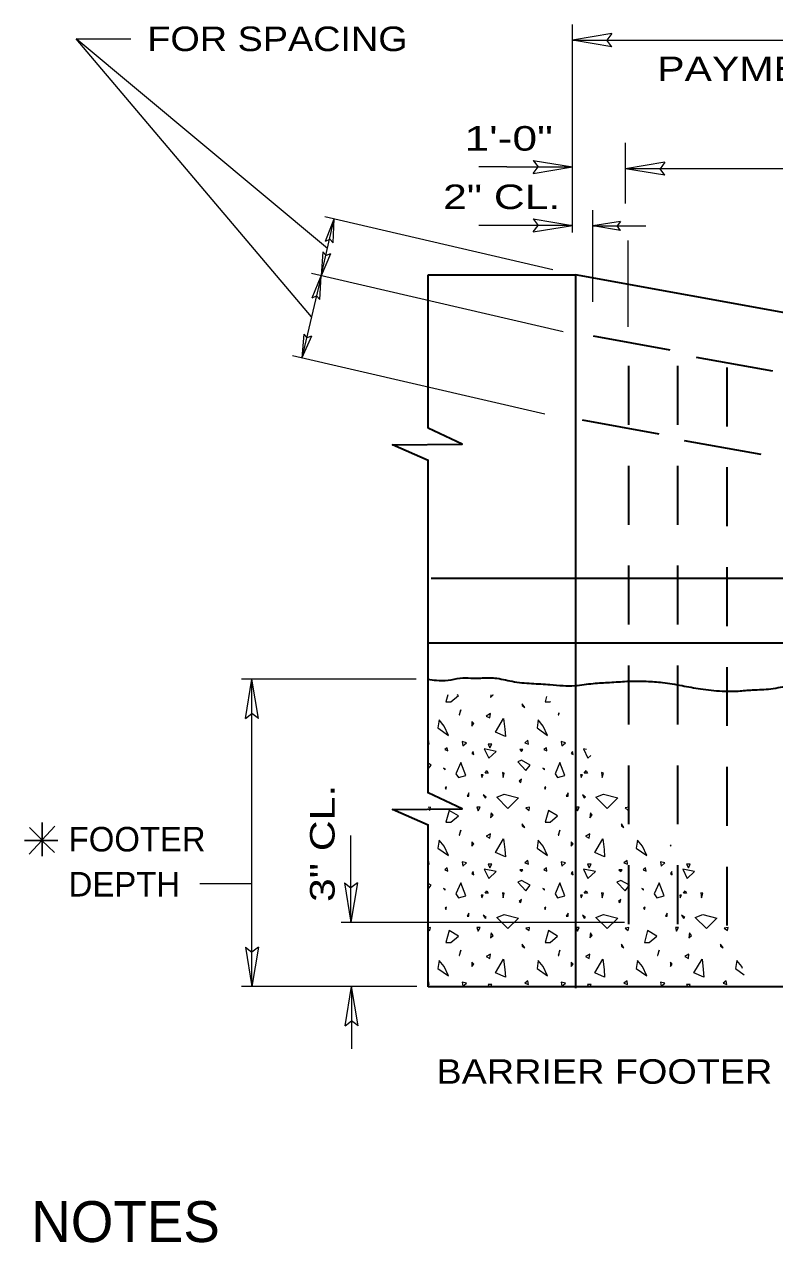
# Model space of a CAD drawing. Extents: x -15.1 to -7.9, y 13.6 to 23.8.
# Drawn here: x -15.107 to -13.275, y 16.661 to 19.638 of the extents above; entities that cross this region are included whole.
import ezdxf
from ezdxf.enums import TextEntityAlignment as Align

# ---------------------------------------------------------------- set-up
doc = ezdxf.new("R2010")
doc.units = 0
doc.header["$LTSCALE"] = 0.024
doc.linetypes.add('LONG_DASHED', pattern=[7.5, 6, -1.5])
for name, color, linetype, lineweight in [('1', 7, 'Continuous', 35), ('10', 7, 'Continuous', 13), ('12', 7, 'Continuous', 53), ('13', 7, 'Continuous', 53), ('6', 7, 'Continuous', 13)]:
    doc.layers.add(name, color=color, linetype=linetype, lineweight=lineweight)

msp = doc.modelspace()

# ---------------------------------------------------------------- linework, layer by layer
at = {"layer": '1'}
for p, q in [((-14.12133, 19.026), (-13.76133, 19.026)), ((-11.781, 18.666), (-13.76133, 19.026)), ((-13.76133, 19.026), (-13.76133, 17.283)), ((-13.53, 18.84183), (-13.71683, 18.87583)), ((-13.27883, 18.79), (-13.46567, 18.824)), ((-13.55717, 18.6365), (-13.74383, 18.67033)), ((-13.30783, 18.5865), (-13.49467, 18.6205)), ((-11.78733, 18.28383), (-14.11333, 18.28383)), ((-11.781, 18.12583), (-14.12133, 18.12583)), ((-11.781, 17.28567), (-14.12133, 17.28567))]:
    msp.add_line(p, q, dxfattribs=at)
at = {"layer": '1', "linetype": 'LONG_DASHED'}
for p, q in [((-13.631, 17.43917), (-13.631, 18.85317)), ((-13.51083, 17.43917), (-13.51083, 18.82083)), ((-13.39083, 17.4355), (-13.39083, 18.81217))]:
    msp.add_line(p, q, dxfattribs=at)
at = {"layer": '1'}
msp.add_spline([(-14.12217, 18.03783), (-14.101, 18.03517), (-14.072, 18.03517), (-14.04283, 18.0405), (-14.0165, 18.0405), (-13.99267, 18.0405), (-13.95833, 18.0405), (-13.916, 18.0325), (-13.86833, 18.02733), (-13.8235, 18.02467), (-13.79167, 18.022), (-13.76267, 18.022), (-13.71767, 18.02733), (-13.678, 18.02983), (-13.63583, 18.0325), (-13.58817, 18.0325), (-13.5485, 18.02983), (-13.501, 18.022), (-13.456, 18.01417), (-13.40317, 18.00883), (-13.3635, 18.00883), (-13.329, 18.0115), (-13.28417, 18.01417), (-13.2365, 18.022), (-13.19167, 18.022), (-13.13083, 18.01933), (-13.09383, 18.00883), (-13.033, 17.993), (-13.01983, 17.99033), (-12.9855, 17.98783), (-12.91933, 17.993), (-12.8955, 17.99567), (-12.85067, 17.99833), (-12.79767, 18.0035), (-12.73433, 18.00617), (-12.68667, 17.99567), (-12.6285, 17.97983), (-12.573, 17.97467), (-12.48583, 17.98517), (-12.34567, 18.0035), (-12.28483, 18.0035), (-12.21617, 17.993), (-12.1315, 17.9825), (-12.01517, 17.97467), (-12.01267, 17.97467), (-12.00467, 17.97467), (-11.97033, 17.972), (-11.92, 17.97733), (-11.88567, 17.98517), (-11.846, 17.99567), (-11.801, 17.99033), (-11.78517, 17.98517)], degree=3, dxfattribs=at)
at = {"layer": '10'}
for p, q in [((-13.76867, 19.12933), (-13.76867, 19.63783)), ((-14.40583, 18.92317), (-14.98083, 19.6025)), ((-13.6725, 19.61517), (-13.76867, 19.59917)), ((-13.76867, 19.59917), (-8.606, 19.59917)), ((-13.6725, 19.58317), (-13.76867, 19.59917)), ((-13.6725, 19.61517), (-13.6845, 19.59917)), ((-13.6725, 19.58317), (-13.6845, 19.59917)), ((-13.63867, 19.19983), (-13.63867, 19.34817)), ((-13.86467, 19.30533), (-13.76867, 19.28933)), ((-13.86467, 19.30533), (-13.85267, 19.28933)), ((-13.54267, 19.30117), (-13.63867, 19.28517)), ((-13.54267, 19.30117), (-13.55467, 19.28517)), ((-13.92867, 19.28933), (-13.99733, 19.28933)), ((-13.92867, 19.28933), (-13.76867, 19.28933)), ((-13.86467, 19.27333), (-13.76867, 19.28933)), ((-13.86467, 19.27333), (-13.85267, 19.28933)), ((-10.09083, 19.28517), (-13.63867, 19.28517)), ((-13.54267, 19.26917), (-13.63867, 19.28517)), ((-13.54267, 19.26917), (-13.55467, 19.28517)), ((-13.7185, 18.96), (-13.7185, 19.18367)), ((-14.3825, 19.02367), (-14.35033, 19.1625)), ((-14.37367, 19.168), (-13.81633, 19.03867)), ((-14.372, 19.10833), (-14.35033, 19.1625)), ((-14.35333, 19.10417), (-14.35033, 19.1625)), ((-13.76867, 19.1465), (-13.99733, 19.1465)), ((-13.86467, 19.1625), (-13.76867, 19.1465)), ((-13.86467, 19.1625), (-13.85267, 19.1465)), ((-13.86467, 19.1305), (-13.76867, 19.1465)), ((-13.86467, 19.1305), (-13.85267, 19.1465)), ((-13.65133, 19.15633), (-13.7185, 19.14517)), ((-13.7185, 19.14517), (-13.5895, 19.14517)), ((-13.65133, 19.134), (-13.7185, 19.14517)), ((-13.65133, 19.15633), (-13.65967, 19.14517)), ((-13.65133, 19.134), (-13.65967, 19.14517)), ((-14.372, 19.10833), (-14.36117, 19.11333)), ((-14.35333, 19.10417), (-14.36117, 19.11333)), ((-13.63217, 18.89867), (-13.63217, 19.10983)), ((-14.37817, 19.082), (-14.3825, 19.02367)), ((-14.3595, 19.07733), (-14.3825, 19.02367)), ((-14.37817, 19.082), (-14.3705, 19.07267)), ((-14.3595, 19.07733), (-14.3705, 19.07267)), ((-14.3825, 19.02367), (-14.42917, 18.82267)), ((-13.79133, 18.88667), (-14.40583, 19.02917)), ((-14.40433, 18.9695), (-14.3825, 19.02367)), ((-14.3855, 18.96533), (-14.3825, 19.02367)), ((-14.40433, 18.9695), (-14.39333, 18.9745)), ((-14.3855, 18.96533), (-14.39333, 18.9745)), ((-14.42483, 18.88083), (-14.42917, 18.82267)), ((-14.40617, 18.87633), (-14.42917, 18.82267)), ((-14.42483, 18.88083), (-14.41717, 18.8715)), ((-14.40617, 18.87633), (-14.41717, 18.8715)), ((-13.83633, 18.68517), (-14.4525, 18.828)), ((-14.1505, 18.03783), (-14.57683, 18.03783)), ((-14.5675, 17.94183), (-14.5515, 18.03783)), ((-14.5515, 17.28667), (-14.5515, 18.03783)), ((-14.5355, 17.94183), (-14.5515, 18.03783)), ((-14.5675, 17.94183), (-14.5515, 17.95383)), ((-14.5355, 17.94183), (-14.5515, 17.95383)), ((-14.3095, 17.444), (-14.3095, 17.6555)), ((-14.679, 17.53867), (-14.55133, 17.53867)), ((-14.3255, 17.54), (-14.3095, 17.444)), ((-14.3255, 17.54), (-14.3095, 17.528)), ((-14.2935, 17.54), (-14.3095, 17.444)), ((-14.2935, 17.54), (-14.3095, 17.528)), ((-14.33317, 17.444), (-13.64133, 17.444)), ((-14.5675, 17.38267), (-14.5515, 17.28667)), ((-14.5675, 17.38267), (-14.5515, 17.37067)), ((-14.5355, 17.38267), (-14.5515, 17.28667)), ((-14.5355, 17.38267), (-14.5515, 17.37067)), ((-14.14883, 17.28667), (-14.57683, 17.28667)), ((-14.32383, 17.19067), (-14.30783, 17.28667)), ((-14.30783, 17.28667), (-14.30783, 17.13433)), ((-14.29183, 17.19067), (-14.30783, 17.28667)), ((-14.32383, 17.19067), (-14.30783, 17.20267)), ((-14.29183, 17.19067), (-14.30783, 17.20267))]:
    msp.add_line(p, q, dxfattribs=at)
at = {"layer": '10', "lineweight": 35}
for p, q in [((-14.12133, 18.651), (-14.12133, 19.026)), ((-14.12133, 17.759), (-14.12133, 18.57367)), ((-14.12133, 17.28567), (-14.12133, 17.68233))]:
    msp.add_line(p, q, dxfattribs=at)
at = {"layer": '10', "lineweight": 25}
for p, q in [((-15.064, 17.60533), (-15.064, 17.68733)), ((-15.09483, 17.675), (-15.0645, 17.64517)), ((-15.06333, 17.64483), (-15.0325, 17.67833)), ((-15.10717, 17.64367), (-15.02517, 17.64367)), ((-15.09533, 17.60983), (-15.0645, 17.6435)), ((-15.06433, 17.64383), (-15.034, 17.614))]:
    msp.add_line(p, q, dxfattribs=at)
at = {"layer": '10'}
msp.add_lwpolyline([(-14.36717, 19.08983), (-14.98083, 19.6025), (-14.847, 19.6025)], dxfattribs=at)
at = {"layer": '10', "lineweight": 35}
for points in [[(-14.12083, 18.57233), (-14.208, 18.6105), (-14.03767, 18.61183), (-14.12083, 18.65133)], [(-14.121, 17.68117), (-14.20817, 17.71933), (-14.03783, 17.72067), (-14.121, 17.76017)]]:
    msp.add_lwpolyline(points, dxfattribs=at)
at = {"layer": '6'}
for points in [[(-14.073, 17.99917), (-14.0775, 17.98217), (-14.0655, 17.98217), (-14.04717, 17.99767), (-14.04983, 17.99917)], [(-13.96783, 17.99917), (-13.96867, 17.993), (-13.9625, 17.99917), (-13.96267, 17.99917)], [(-13.83167, 17.99517), (-13.83517, 17.98217), (-13.82317, 17.98217), (-13.8225, 17.98283)], [(-13.80167, 17.95533), (-13.8035, 17.9505), (-13.802, 17.9505), (-13.801, 17.9545)], [(-14.12133, 17.88033), (-14.1185, 17.87917), (-14.12, 17.88867), (-14.12133, 17.8875)], [(-13.73433, 17.86583), (-13.7415, 17.86733), (-13.73067, 17.84467), (-13.72333, 17.85133)], [(-14.12133, 17.8185), (-14.11383, 17.82783), (-14.12133, 17.83217)], [(-14.12133, 17.72067), (-14.117, 17.71717), (-14.11567, 17.72483), (-14.12133, 17.72383)], [(-13.5295, 17.63333), (-13.5295, 17.62933), (-13.5275, 17.632)], [(-14.12133, 17.5865), (-14.1185, 17.5855), (-14.12, 17.59483), (-14.12133, 17.59367)], [(-14.12133, 17.52467), (-14.11383, 17.534), (-14.12133, 17.53833)], [(-14.12133, 17.42683), (-14.117, 17.42333), (-14.11567, 17.431), (-14.12133, 17.43)], [(-13.35317, 17.33117), (-13.35517, 17.3355), (-13.36733, 17.35067), (-13.37033, 17.33117), (-13.34883, 17.31567)], [(-14.12133, 17.29267), (-14.1185, 17.29167), (-14.12, 17.301), (-14.12133, 17.29983)], [(-13.9685, 17.28567), (-13.9655, 17.29167), (-13.9745, 17.29167), (-13.97167, 17.28567)], [(-13.72617, 17.28567), (-13.72317, 17.29167), (-13.73217, 17.29167), (-13.72933, 17.28567)], [(-13.48383, 17.28567), (-13.48083, 17.29167), (-13.48983, 17.29167), (-13.487, 17.28567)]]:
    msp.add_lwpolyline(points, dxfattribs=at)
for points in [[(-14.04567, 17.9505), (-14.04433, 17.9505), (-14.0415, 17.96283)], [(-13.97917, 17.94767), (-13.97017, 17.943), (-13.96867, 17.95383)], [(-13.89133, 17.97783), (-13.89133, 17.97317), (-13.88517, 17.96883)], [(-14.09433, 17.93833), (-14.09717, 17.91883), (-14.07167, 17.9005), (-14.08217, 17.92317)], [(-14.014, 17.934), (-14.014, 17.92317), (-14.00933, 17.92933)], [(-13.93383, 17.91567), (-13.93233, 17.89767), (-13.9565, 17.908), (-13.93667, 17.9415)], [(-13.852, 17.93833), (-13.855, 17.91883), (-13.82933, 17.9005), (-13.83983, 17.92317)], [(-14.08067, 17.86583), (-14.07317, 17.86267), (-14.0745, 17.87017)], [(-14.03817, 17.88533), (-14.03667, 17.875), (-14.02767, 17.8825)], [(-13.98383, 17.86733), (-13.973, 17.84467), (-13.955, 17.86117)], [(-13.9745, 17.87917), (-13.97017, 17.87017), (-13.9655, 17.87917)], [(-13.89733, 17.86583), (-13.89267, 17.86117), (-13.88983, 17.86583)], [(-13.87767, 17.88867), (-13.88517, 17.8825), (-13.87617, 17.87917)], [(-13.83833, 17.86583), (-13.83083, 17.86267), (-13.83217, 17.87017)], [(-13.79583, 17.88533), (-13.7945, 17.875), (-13.7855, 17.8825)], [(-14.04717, 17.7975), (-14.02917, 17.80217), (-14.0415, 17.83383), (-14.05333, 17.80683)], [(-14.014, 17.8565), (-14.00933, 17.85367), (-14.01083, 17.86117)], [(-13.90217, 17.83567), (-13.88233, 17.8145), (-13.8715, 17.82783), (-13.89267, 17.84)], [(-13.80483, 17.7975), (-13.78683, 17.80217), (-13.79917, 17.83383), (-13.811, 17.80683)], [(-13.77167, 17.8565), (-13.767, 17.85367), (-13.7685, 17.86117)], [(-14.07917, 17.81867), (-14.0835, 17.82017), (-14.07917, 17.81583)], [(-13.99133, 17.80367), (-13.99, 17.7975), (-13.98667, 17.80367)], [(-13.97767, 17.8145), (-13.9745, 17.80833), (-13.982, 17.80833)], [(-13.93983, 17.80967), (-13.93817, 17.7975), (-13.93517, 17.80833)], [(-13.83683, 17.81867), (-13.84117, 17.82017), (-13.83683, 17.81583)], [(-13.749, 17.80367), (-13.74767, 17.7975), (-13.74433, 17.80367)], [(-13.73533, 17.8145), (-13.73217, 17.80833), (-13.73967, 17.80833)], [(-13.6975, 17.80967), (-13.69583, 17.7975), (-13.69283, 17.80833)], [(-14.076, 17.77483), (-14.07917, 17.772), (-14.0775, 17.76867)], [(-13.89883, 17.7885), (-13.8945, 17.78567), (-13.89267, 17.79317)], [(-13.83367, 17.77483), (-13.83683, 17.772), (-13.83517, 17.76867)], [(-14.02167, 17.75967), (-14.026, 17.75217), (-14.02167, 17.75217)], [(-13.982, 17.74783), (-13.97917, 17.74933), (-13.98667, 17.75533)], [(-13.93517, 17.75683), (-13.90033, 17.74783), (-13.92617, 17.72183), (-13.9535, 17.74933)], [(-13.77933, 17.75967), (-13.78367, 17.75217), (-13.77933, 17.75217)], [(-13.73967, 17.74783), (-13.73683, 17.74933), (-13.74433, 17.75533)], [(-13.69283, 17.75683), (-13.658, 17.74783), (-13.68383, 17.72183), (-13.71133, 17.74933)], [(-14.0655, 17.68833), (-14.04717, 17.70383), (-14.06983, 17.71717), (-14.0775, 17.68833)], [(-14.00183, 17.72483), (-13.999, 17.71583), (-13.99433, 17.72483)], [(-13.88233, 17.72333), (-13.87467, 17.71717), (-13.87333, 17.72483)], [(-13.82317, 17.68833), (-13.80483, 17.70383), (-13.8275, 17.71717), (-13.83517, 17.68833)], [(-13.7595, 17.72483), (-13.75667, 17.71583), (-13.752, 17.72483)], [(-13.64, 17.72333), (-13.63233, 17.71717), (-13.631, 17.72483)], [(-13.96683, 17.7115), (-13.96867, 17.69917), (-13.9625, 17.70533)], [(-13.89133, 17.68417), (-13.89133, 17.67933), (-13.88517, 17.67517)], [(-13.7245, 17.7115), (-13.72633, 17.69917), (-13.72033, 17.70533)], [(-13.649, 17.68417), (-13.649, 17.67933), (-13.64283, 17.67517)], [(-14.04567, 17.65667), (-14.04433, 17.65667), (-14.0415, 17.669)], [(-13.97917, 17.65383), (-13.97017, 17.64917), (-13.96867, 17.66)], [(-13.8035, 17.65667), (-13.802, 17.65667), (-13.79917, 17.669)], [(-13.73683, 17.65383), (-13.72783, 17.64917), (-13.72633, 17.66)], [(-14.09433, 17.6445), (-14.09717, 17.625), (-14.07167, 17.60667), (-14.08217, 17.62933)], [(-14.014, 17.64017), (-14.014, 17.62933), (-14.00933, 17.6355)], [(-13.93383, 17.62183), (-13.93233, 17.60383), (-13.9565, 17.61417), (-13.93667, 17.64767)], [(-13.852, 17.6445), (-13.855, 17.625), (-13.82933, 17.60667), (-13.83983, 17.62933)], [(-13.77167, 17.64017), (-13.77167, 17.62933), (-13.767, 17.6355)], [(-13.6915, 17.62183), (-13.69, 17.60383), (-13.71417, 17.61417), (-13.69433, 17.64767)], [(-13.60967, 17.6445), (-13.61267, 17.625), (-13.587, 17.60667), (-13.5975, 17.62933)], [(-13.87767, 17.59483), (-13.88517, 17.58867), (-13.87617, 17.5855)], [(-13.63533, 17.59483), (-13.64283, 17.58867), (-13.63383, 17.5855)], [(-14.08067, 17.57217), (-14.07317, 17.56883), (-14.0745, 17.5765)], [(-14.03817, 17.5915), (-14.03667, 17.58117), (-14.02767, 17.58867)], [(-14.014, 17.56267), (-14.00933, 17.55983), (-14.01083, 17.5675)], [(-13.98383, 17.5735), (-13.973, 17.55083), (-13.955, 17.5675)], [(-13.9745, 17.5855), (-13.97017, 17.5765), (-13.9655, 17.5855)], [(-13.89733, 17.57217), (-13.89267, 17.5675), (-13.88983, 17.57217)], [(-13.83833, 17.57217), (-13.83083, 17.56883), (-13.83217, 17.5765)], [(-13.79583, 17.5915), (-13.7945, 17.58117), (-13.7855, 17.58867)], [(-13.77167, 17.56267), (-13.767, 17.55983), (-13.7685, 17.5675)], [(-13.7415, 17.5735), (-13.73067, 17.55083), (-13.71267, 17.5675)], [(-13.73217, 17.5855), (-13.72783, 17.5765), (-13.72317, 17.5855)], [(-13.65517, 17.57217), (-13.65033, 17.5675), (-13.6475, 17.57217)], [(-13.596, 17.57217), (-13.5885, 17.56883), (-13.58983, 17.5765)], [(-13.5535, 17.5915), (-13.55217, 17.58117), (-13.54317, 17.58867)], [(-13.5295, 17.56267), (-13.52467, 17.55983), (-13.52617, 17.5675)], [(-13.49917, 17.5735), (-13.48833, 17.55083), (-13.47033, 17.5675)], [(-13.48983, 17.5855), (-13.4855, 17.5765), (-13.48083, 17.5855)], [(-14.04717, 17.50367), (-14.02917, 17.50833), (-14.0415, 17.54), (-14.05333, 17.513)], [(-13.90217, 17.54183), (-13.88233, 17.52067), (-13.8715, 17.534), (-13.89267, 17.54617)], [(-13.80483, 17.50367), (-13.78683, 17.50833), (-13.79917, 17.54), (-13.811, 17.513)], [(-13.65983, 17.54183), (-13.64, 17.52067), (-13.62917, 17.534), (-13.65033, 17.54617)], [(-13.5625, 17.50367), (-13.5445, 17.50833), (-13.55683, 17.54), (-13.56867, 17.513)], [(-14.07917, 17.525), (-14.0835, 17.52633), (-14.07917, 17.522)], [(-13.99133, 17.50983), (-13.99, 17.50367), (-13.98667, 17.50983)], [(-13.97767, 17.52067), (-13.9745, 17.5145), (-13.982, 17.5145)], [(-13.93983, 17.516), (-13.93817, 17.50367), (-13.93517, 17.5145)], [(-13.83683, 17.525), (-13.84117, 17.52633), (-13.83683, 17.522)], [(-13.749, 17.50983), (-13.74767, 17.50367), (-13.74433, 17.50983)], [(-13.73533, 17.52067), (-13.73217, 17.5145), (-13.73967, 17.5145)], [(-13.6975, 17.516), (-13.69583, 17.50367), (-13.69283, 17.5145)], [(-13.59467, 17.525), (-13.599, 17.52633), (-13.59467, 17.522)], [(-13.50667, 17.50983), (-13.50533, 17.50367), (-13.502, 17.50983)], [(-13.493, 17.52067), (-13.48983, 17.5145), (-13.49733, 17.5145)], [(-13.45533, 17.516), (-13.4535, 17.50367), (-13.4505, 17.5145)], [(-14.076, 17.481), (-14.07917, 17.47817), (-14.0775, 17.47483)], [(-13.89883, 17.49467), (-13.8945, 17.49183), (-13.89267, 17.49933)], [(-13.83367, 17.481), (-13.83683, 17.47817), (-13.83517, 17.47483)], [(-13.6565, 17.49467), (-13.65217, 17.49183), (-13.65033, 17.49933)], [(-13.59133, 17.481), (-13.59467, 17.47817), (-13.59283, 17.47483)], [(-14.02167, 17.46583), (-14.026, 17.45833), (-14.02167, 17.45833)], [(-13.982, 17.454), (-13.97917, 17.4555), (-13.98667, 17.4615)], [(-13.93517, 17.463), (-13.90033, 17.454), (-13.92617, 17.42817), (-13.9535, 17.4555)], [(-13.77933, 17.46583), (-13.78367, 17.45833), (-13.77933, 17.45833)], [(-13.73967, 17.454), (-13.73683, 17.4555), (-13.74433, 17.4615)], [(-13.69283, 17.463), (-13.658, 17.454), (-13.68383, 17.42817), (-13.71133, 17.4555)], [(-13.537, 17.46583), (-13.54133, 17.45833), (-13.537, 17.45833)], [(-13.49733, 17.454), (-13.4945, 17.4555), (-13.502, 17.4615)], [(-13.4505, 17.463), (-13.41567, 17.454), (-13.4415, 17.42817), (-13.469, 17.4555)], [(-14.0655, 17.39467), (-14.04717, 17.41017), (-14.06983, 17.42333), (-14.0775, 17.39467)], [(-14.00183, 17.431), (-13.999, 17.422), (-13.99433, 17.431)], [(-13.96683, 17.41767), (-13.96867, 17.40533), (-13.9625, 17.4115)], [(-13.88233, 17.4295), (-13.87467, 17.42333), (-13.87333, 17.431)], [(-13.82317, 17.39467), (-13.80483, 17.41017), (-13.8275, 17.42333), (-13.83517, 17.39467)], [(-13.7595, 17.431), (-13.75667, 17.422), (-13.752, 17.431)], [(-13.7245, 17.41767), (-13.72633, 17.40533), (-13.72033, 17.4115)], [(-13.64, 17.4295), (-13.63233, 17.42333), (-13.631, 17.431)], [(-13.58083, 17.39467), (-13.5625, 17.41017), (-13.58517, 17.42333), (-13.59283, 17.39467)], [(-13.51717, 17.431), (-13.51433, 17.422), (-13.50967, 17.431)], [(-13.48233, 17.41767), (-13.484, 17.40533), (-13.478, 17.4115)], [(-13.39767, 17.4295), (-13.39017, 17.42333), (-13.38867, 17.431)], [(-13.89133, 17.39033), (-13.89133, 17.38567), (-13.88517, 17.38133)], [(-13.649, 17.39033), (-13.649, 17.38567), (-13.64283, 17.38133)], [(-13.40667, 17.39033), (-13.40667, 17.38567), (-13.4005, 17.38133)], [(-14.04567, 17.36283), (-14.04433, 17.36283), (-14.0415, 17.37517)], [(-13.97917, 17.36), (-13.97017, 17.35533), (-13.96867, 17.36617)], [(-13.8035, 17.36283), (-13.802, 17.36283), (-13.79917, 17.37517)], [(-13.73683, 17.36), (-13.72783, 17.35533), (-13.72633, 17.36617)], [(-13.56117, 17.36283), (-13.55967, 17.36283), (-13.55683, 17.37517)], [(-13.4945, 17.36), (-13.4855, 17.35533), (-13.484, 17.36617)], [(-14.09433, 17.35067), (-14.09717, 17.33117), (-14.07167, 17.31283), (-14.08217, 17.3355)], [(-14.014, 17.34633), (-14.014, 17.3355), (-14.00933, 17.34167)], [(-13.93383, 17.328), (-13.93233, 17.31), (-13.9565, 17.3205), (-13.93667, 17.35383)], [(-13.852, 17.35067), (-13.855, 17.33117), (-13.82933, 17.31283), (-13.83983, 17.3355)], [(-13.77167, 17.34633), (-13.77167, 17.3355), (-13.767, 17.34167)], [(-13.6915, 17.328), (-13.69, 17.31), (-13.71417, 17.3205), (-13.69433, 17.35383)], [(-13.60967, 17.35067), (-13.61267, 17.33117), (-13.587, 17.31283), (-13.5975, 17.3355)], [(-13.5295, 17.34633), (-13.5295, 17.3355), (-13.52467, 17.34167)], [(-13.44917, 17.328), (-13.44767, 17.31), (-13.47183, 17.3205), (-13.452, 17.35383)], [(-14.03817, 17.29767), (-14.03667, 17.28733), (-14.02767, 17.29483)], [(-13.87767, 17.301), (-13.88517, 17.29483), (-13.87617, 17.29167)], [(-13.79583, 17.29767), (-13.7945, 17.28733), (-13.7855, 17.29483)], [(-13.63533, 17.301), (-13.64283, 17.29483), (-13.63383, 17.29167)], [(-13.5535, 17.29767), (-13.55217, 17.28733), (-13.54317, 17.29483)], [(-13.393, 17.301), (-13.4005, 17.29483), (-13.3915, 17.29167)]]:
    msp.add_lwpolyline(points, close=True, dxfattribs=at)

# ---------------------------------------------------------------- texts
at = {"layer": '12', "width": 1.15}
msp.add_text('FOR SPACING', height=0.06001, dxfattribs=at).set_placement((-14.80692, 19.5725))
at = {"layer": '12'}
for s, width, p in [('PAYMENT PER EACH FOR F SHAPE CONCRETE TRAFFIC BARRIER SINGLE FACE END TRANSITION', 1.25, (-11.15954, 19.49917)), ('1\'-0"', 1.35, (-13.92433, 19.32925)), ('2" CL.', 1.3, (-13.94137, 19.18642))]:
    msp.add_text(s, height=0.06001, dxfattribs=dict(at, width=width)).set_placement(p, align=Align.CENTER)
at = {"layer": '12', "width": 1.3}
msp.add_text('3" CL.', height=0.06001, rotation=90, dxfattribs=at).set_placement((-14.3495, 17.6365), align=Align.CENTER)
at = {"layer": '12'}
for s, p in [('FOOTER', (-14.99892, 17.61675)), ('DEPTH', (-14.99892, 17.50667))]:
    msp.add_text(s, height=0.06001, dxfattribs=at).set_placement(p)
at = {"layer": '12', "width": 1.15}
msp.add_text('BARRIER FOOTER', height=0.06001, dxfattribs=at).set_placement((-13.28042, 17.04908), align=Align.RIGHT)
at = {"layer": '13'}
msp.add_text('NOTES', height=0.1, dxfattribs=at).set_placement((-15.09042, 16.66233))

doc.saveas('drawing.dxf')
